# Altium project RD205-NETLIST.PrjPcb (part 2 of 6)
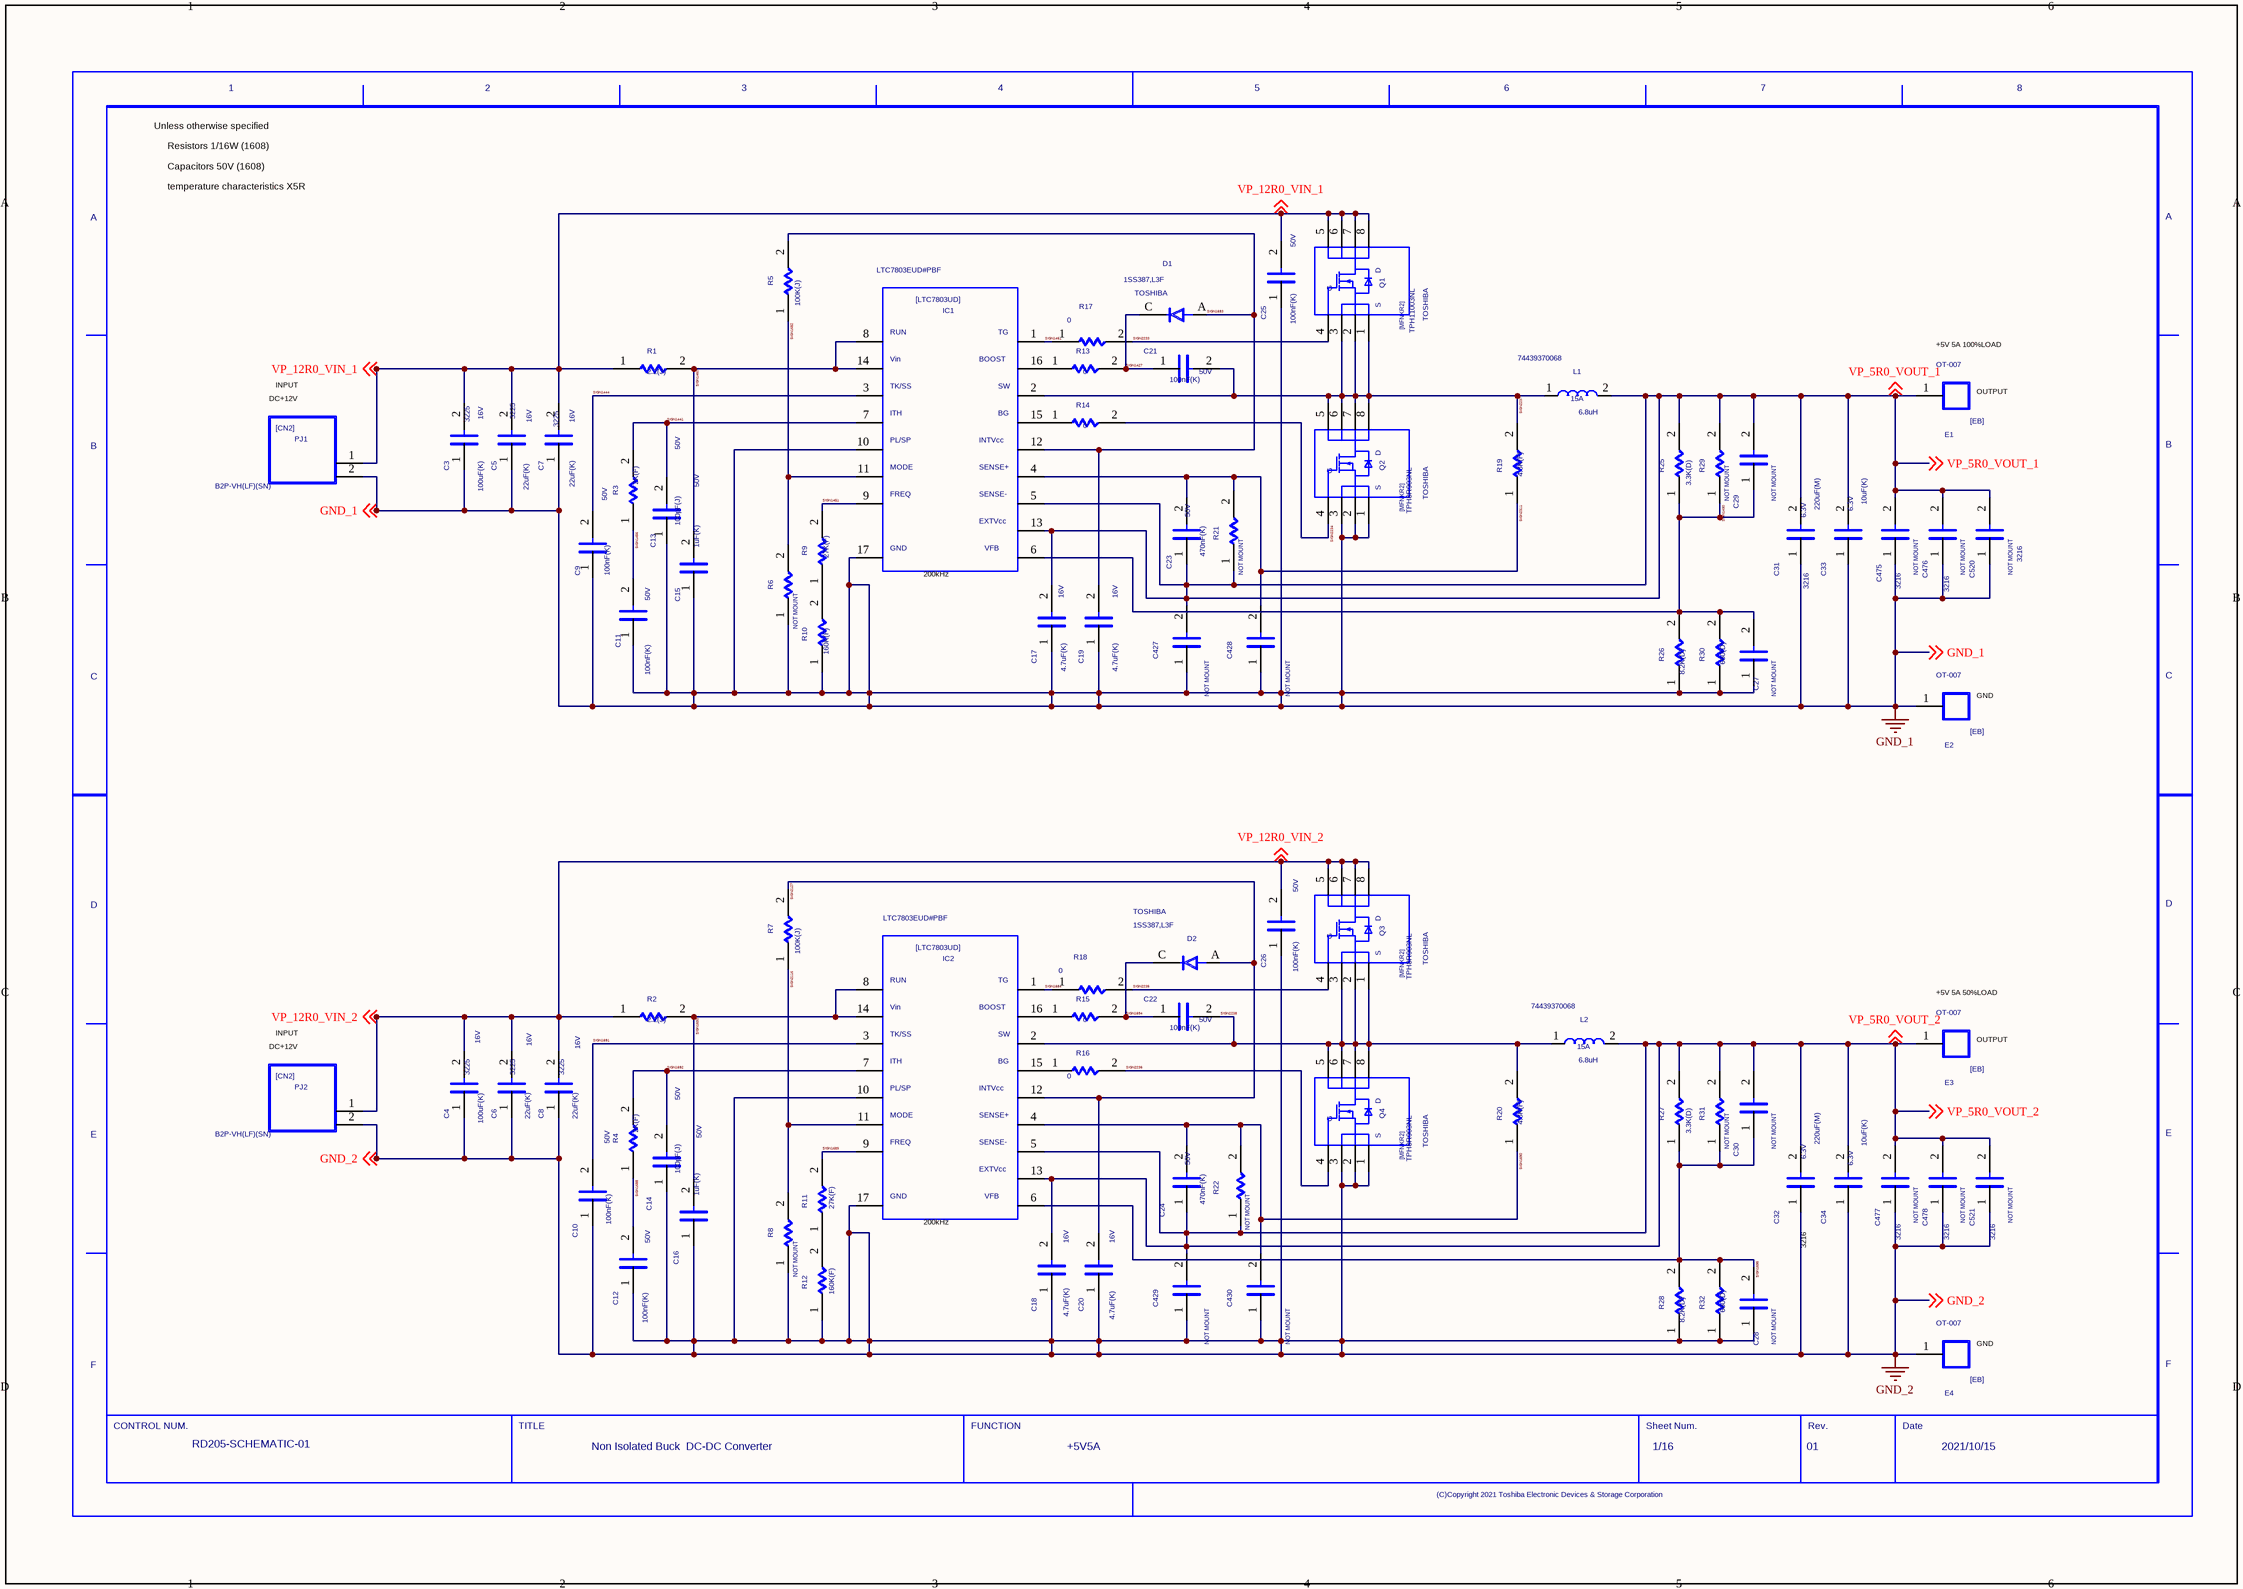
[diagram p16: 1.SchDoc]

## Sheet 1.SchDoc (continued)

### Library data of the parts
C3 = C_Dup1: SQ_PART_MODEL: CON_100n; FNPARTSNAMEG: CHIP CERAMIC CAPACITOR (3225); USEINPARTSLIST: YES; OriginalSymbolOrigin: (2540,7620); OLDCOMPONENTID: 209; MFSOLDERINGPROP: .; TEMPCHARACTERI2: B; MFFORMINGDIVP: KC; OUMECLASSIFICATION: セラミックコンデンサ; MFMOUNTSYMBOLP: 90; CDMASTERCADCELG: DC903A; PCODE: P03276001115; FNCLASSCODEG: P03-03; MAXGCOUNT: 1; RATEDVOLTAGE: 250; COMPONENTNAME: G36030160049; OUMEMAKER: KYC 京セラ; MFPACKAGEMETHOP: S; NOMINALCAPACITA: 100n; OUMEMAKERKATAMEI: CF32W5R104K250AT; CAPACITANCETOLE: K
C4 = C_Dup1: SQ_PART_MODEL: CON_100n; FNPARTSNAMEG: CHIP CERAMIC CAPACITOR (3225); USEINPARTSLIST: YES; OriginalSymbolOrigin: (2540,7620); OLDCOMPONENTID: 396; MFSOLDERINGPROP: .; TEMPCHARACTERI2: B; MFFORMINGDIVP: KC; OUMECLASSIFICATION: セラミックコンデンサ; MFMOUNTSYMBOLP: 90; CDMASTERCADCELG: DC903A; PCODE: P03276001115; FNCLASSCODEG: P03-03; MAXGCOUNT: 1; RATEDVOLTAGE: 250; COMPONENTNAME: G36030160049; OUMEMAKER: KYC 京セラ; MFPACKAGEMETHOP: S; NOMINALCAPACITA: 100n; OUMEMAKERKATAMEI: CF32W5R104K250AT; CAPACITANCETOLE: K
C5 = C_Dup1: SQ_PART_MODEL: CON_22u; FNPARTSNAMEG: CHIP CERAMIC CAPACITOR (3225); USEINPARTSLIST: YES; OriginalSymbolOrigin: (2540,7620); OLDCOMPONENTID: 195; MFSOLDERINGPROP: .; TEMPCHARACTERI2: B; MFFORMINGDIVP: KC; OUMECLASSIFICATION: セラミックコンデンサ; MFMOUNTSYMBOLP: 80; CDMASTERCADCELG: DC903A; PCODE: P03043035626; FNCLASSCODEG: P03-03; MAXGCOUNT: 1; RATEDVOLTAGE: 6.3; COMPONENTNAME: G36030119054; OUMEMAKER: TYD 太陽誘電; MFPACKAGEMETHOP: S; NOMINALCAPACITA: 22u; OUMEMAKERKATAMEI: JMK325BJ226KM-T; CAPACITANCETOLE: K
C6 = C_Dup1: SQ_PART_MODEL: CON_22u; FNPARTSNAMEG: CHIP CERAMIC CAPACITOR (3225); USEINPARTSLIST: YES; OriginalSymbolOrigin: (2540,7620); OLDCOMPONENTID: 358; MFSOLDERINGPROP: .; TEMPCHARACTERI2: B; MFFORMINGDIVP: KC; OUMECLASSIFICATION: セラミックコンデンサ; MFMOUNTSYMBOLP: 80; CDMASTERCADCELG: DC903A; PCODE: P03043035626; FNCLASSCODEG: P03-03; MAXGCOUNT: 1; RATEDVOLTAGE: 6.3; COMPONENTNAME: G36030119054; OUMEMAKER: TYD 太陽誘電; MFPACKAGEMETHOP: S; NOMINALCAPACITA: 22u; OUMEMAKERKATAMEI: JMK325BJ226KM-T; CAPACITANCETOLE: K
C7 = C_Dup1: SQ_PART_MODEL: CON_22u; FNPARTSNAMEG: CHIP CERAMIC CAPACITOR (3225); USEINPARTSLIST: YES; OriginalSymbolOrigin: (2540,7620); OLDCOMPONENTID: 230; MFSOLDERINGPROP: .; TEMPCHARACTERI2: B; MFFORMINGDIVP: KC; OUMECLASSIFICATION: セラミックコンデンサ; MFMOUNTSYMBOLP: 80; CDMASTERCADCELG: DC903A; PCODE: P03043035626; FNCLASSCODEG: P03-03; MAXGCOUNT: 1; RATEDVOLTAGE: 6.3; COMPONENTNAME: G36030119054; OUMEMAKER: TYD 太陽誘電; MFPACKAGEMETHOP: S; NOMINALCAPACITA: 22u; OUMEMAKERKATAMEI: JMK325BJ226KM-T; CAPACITANCETOLE: K
C8 = C_Dup1: SQ_PART_MODEL: CON_22u; FNPARTSNAMEG: CHIP CERAMIC CAPACITOR (3225); USEINPARTSLIST: YES; OriginalSymbolOrigin: (2540,7620); OLDCOMPONENTID: 386; MFSOLDERINGPROP: .; TEMPCHARACTERI2: B; MFFORMINGDIVP: KC; OUMECLASSIFICATION: セラミックコンデンサ; MFMOUNTSYMBOLP: 80; CDMASTERCADCELG: DC903A; PCODE: P03043035626; FNCLASSCODEG: P03-03; MAXGCOUNT: 1; RATEDVOLTAGE: 6.3; COMPONENTNAME: G36030119054; OUMEMAKER: TYD 太陽誘電; MFPACKAGEMETHOP: S; NOMINALCAPACITA: 22u; OUMEMAKERKATAMEI: JMK325BJ226KM-T; CAPACITANCETOLE: K
C9 = C_Dup1: SQ_PART_MODEL: CON_100n; FNPARTSNAMEG: CHIP CERAMIC CAPACITOR (1608); USEINPARTSLIST: YES; OriginalSymbolOrigin: (2540,7620); OLDCOMPONENTID: 199; MFSOLDERINGPROP: .; TEMPCHARACTERI2: B; MFFORMINGDIVP: KC; OUMECLASSIFICATION: セラミックコンデンサ; SIZECODESMD: 1608; MFMOUNTSYMBOLP: 80; CDMASTERCADCELG: C8100E; PCODE: P03B000000E4; FNCLASSCODEG: P03-03; MAXGCOUNT: 1; RATEDVOLTAGE: 16; COMPONENTNAME: GDM030000598; OUMEMAKER: MRT 村田製作所; MFPACKAGEMETHOP: S; NOMINALCAPACITA: 100n; OUMEMAKERKATAMEI: GRM188B11C104KA01C; CAPACITANCETOLE: K
C10 = C_Dup1: SQ_PART_MODEL: CON_100n; FNPARTSNAMEG: CHIP CERAMIC CAPACITOR (1608); USEINPARTSLIST: YES; OriginalSymbolOrigin: (2540,7620); OLDCOMPONENTID: 349; MFSOLDERINGPROP: .; TEMPCHARACTERI2: B; MFFORMINGDIVP: KC; OUMECLASSIFICATION: セラミックコンデンサ; SIZECODESMD: 1608; MFMOUNTSYMBOLP: 80; CDMASTERCADCELG: C8100E; PCODE: P03B000000E4; FNCLASSCODEG: P03-03; MAXGCOUNT: 1; RATEDVOLTAGE: 16; COMPONENTNAME: GDM030000598; OUMEMAKER: MRT 村田製作所; MFPACKAGEMETHOP: S; NOMINALCAPACITA: 100n; OUMEMAKERKATAMEI: GRM188B11C104KA01C; CAPACITANCETOLE: K
C11 = C_Dup1: SQ_PART_MODEL: CON_100n; FNPARTSNAMEG: CHIP CERAMIC CAPACITOR (1608); USEINPARTSLIST: YES; OriginalSymbolOrigin: (2540,7620); OLDCOMPONENTID: 173; MFSOLDERINGPROP: .; TEMPCHARACTERI2: B; MFFORMINGDIVP: KC; OUMECLASSIFICATION: セラミックコンデンサ; SIZECODESMD: 1608; MFMOUNTSYMBOLP: 80; CDMASTERCADCELG: C8100E; PCODE: P03B000000E4; FNCLASSCODEG: P03-03; MAXGCOUNT: 1; RATEDVOLTAGE: 16; COMPONENTNAME: GDM030000598; OUMEMAKER: MRT 村田製作所; MFPACKAGEMETHOP: S; NOMINALCAPACITA: 100n; OUMEMAKERKATAMEI: GRM188B11C104KA01C; CAPACITANCETOLE: K
C12 = C_Dup1: SQ_PART_MODEL: CON_100n; FNPARTSNAMEG: CHIP CERAMIC CAPACITOR (1608); USEINPARTSLIST: YES; OriginalSymbolOrigin: (2540,7620); OLDCOMPONENTID: 400; MFSOLDERINGPROP: .; TEMPCHARACTERI2: B; MFFORMINGDIVP: KC; OUMECLASSIFICATION: セラミックコンデンサ; SIZECODESMD: 1608; MFMOUNTSYMBOLP: 80; CDMASTERCADCELG: C8100E; PCODE: P03B000000E4; FNCLASSCODEG: P03-03; MAXGCOUNT: 1; RATEDVOLTAGE: 16; COMPONENTNAME: GDM030000598; OUMEMAKER: MRT 村田製作所; MFPACKAGEMETHOP: S; NOMINALCAPACITA: 100n; OUMEMAKERKATAMEI: GRM188B11C104KA01C; CAPACITANCETOLE: K
C13 = C_Dup1: SQ_PART_MODEL: CON_100p; FNPARTSNAMEG: CHIP CERAMIC CAPACITOR (1608); USEINPARTSLIST: YES; OriginalSymbolOrigin: (2540,7620); OLDCOMPONENTID: 206; TOLERANCE: J; ASIMVALUE: 100P; MFSOLDERINGPROP: .; TEMPCHARACTERI2: CH; MFFORMINGDIVP: KC; OUMECLASSIFICATION: セラミックコンデンサ; SIZECODESMD: 1608; MFMOUNTSYMBOLP: 80; CDMASTERCADCELG: C8100E; PCODE: P03039177125; FNCLASSCODEG: P03-03; MAXGCOUNT: 1; RATEDVOLTAGE: 50; COMPONENTNAME: G36030011365; OUMEMAKER: KYC 京セラ; MFPACKAGEMETHOP: S; OUMEMAKERKATAMEI: CM105CH101J50AT
C14 = C_Dup1: SQ_PART_MODEL: CON_100p; FNPARTSNAMEG: CHIP CERAMIC CAPACITOR (1608); USEINPARTSLIST: YES; OriginalSymbolOrigin: (2540,7620); OLDCOMPONENTID: 397; TOLERANCE: J; ASIMVALUE: 100P; MFSOLDERINGPROP: .; TEMPCHARACTERI2: CH; MFFORMINGDIVP: KC; OUMECLASSIFICATION: セラミックコンデンサ; SIZECODESMD: 1608; MFMOUNTSYMBOLP: 80; CDMASTERCADCELG: C8100E; PCODE: P03039177125; FNCLASSCODEG: P03-03; MAXGCOUNT: 1; RATEDVOLTAGE: 50; COMPONENTNAME: G36030011365; OUMEMAKER: KYC 京セラ; MFPACKAGEMETHOP: S; OUMEMAKERKATAMEI: CM105CH101J50AT
C15 = C_Dup1: SQ_PART_MODEL: CON_1u; FNPARTSNAMEG: CHIP CERAMIC CAPACITOR (1608); USEINPARTSLIST: YES; OriginalSymbolOrigin: (2540,7620); OLDCOMPONENTID: 176; MFSOLDERINGPROP: .; TEMPCHARACTERI2: B; MFFORMINGDIVP: KC; OUMECLASSIFICATION: セラミックコンデンサ; SIZECODESMD: 1608; MFMOUNTSYMBOLP: 80; CDMASTERCADCELG: C8100E; PCODE: P03039ACE122; FNCLASSCODEG: P03-03; MAXGCOUNT: 1; RATEDVOLTAGE: 6.3; COMPONENTNAME: G36030104159; OUMEMAKER: KYC 京セラ; MFPACKAGEMETHOP: S; NOMINALCAPACITA: 1u; OUMEMAKERKATAMEI: CM105B105K06ATN; CAPACITANCETOLE: K
C16 = C_Dup1: SQ_PART_MODEL: CON_1u; FNPARTSNAMEG: CHIP CERAMIC CAPACITOR (1608); USEINPARTSLIST: YES; OriginalSymbolOrigin: (2540,7620); OLDCOMPONENTID: 368; MFSOLDERINGPROP: .; TEMPCHARACTERI2: B; MFFORMINGDIVP: KC; OUMECLASSIFICATION: セラミックコンデンサ; SIZECODESMD: 1608; MFMOUNTSYMBOLP: 80; CDMASTERCADCELG: C8100E; PCODE: P03039ACE122; FNCLASSCODEG: P03-03; MAXGCOUNT: 1; RATEDVOLTAGE: 6.3; COMPONENTNAME: G36030104159; OUMEMAKER: KYC 京セラ; MFPACKAGEMETHOP: S; NOMINALCAPACITA: 1u; OUMEMAKERKATAMEI: CM105B105K06ATN; CAPACITANCETOLE: K
C17 = C_Dup1: SQ_PART_MODEL: CON_4.7u; FNPARTSNAMEG: CHIP CERAMIC CAPACITOR (1608); USEINPARTSLIST: YES; OriginalSymbolOrigin: (2540,7620); OLDCOMPONENTID: 178; PCODE: P03B000000MS; MFSOLDERINGPROP: .; TEMPCHARACTERI2: B; MFFORMINGDIVP: KC; OUMECLASSIFICATION: セラミックコンデンサ; SIZECODESMD: 1608; MFMOUNTSYMBOLP: 80; CDMASTERCADCELG: C8100E; FNCLASSCODEG: P03-03; MAXGCOUNT: 1; RATEDVOLTAGE: 4; COMPONENTNAME: GDM030000053; OUMEMAKER: KYC 京セラ; MFPACKAGEMETHOP: S; NOMINALCAPACITA: 4.7u; OUMEMAKERKATAMEI: CM105B475M04AT; CAPACITANCETOLE: M
C18 = C_Dup1: SQ_PART_MODEL: CON_4.7u; FNPARTSNAMEG: CHIP CERAMIC CAPACITOR (1608); USEINPARTSLIST: YES; OriginalSymbolOrigin: (2540,7620); OLDCOMPONENTID: 389; PCODE: P03B000000MS; MFSOLDERINGPROP: .; TEMPCHARACTERI2: B; MFFORMINGDIVP: KC; OUMECLASSIFICATION: セラミックコンデンサ; SIZECODESMD: 1608; MFMOUNTSYMBOLP: 80; CDMASTERCADCELG: C8100E; FNCLASSCODEG: P03-03; MAXGCOUNT: 1; RATEDVOLTAGE: 4; COMPONENTNAME: GDM030000053; OUMEMAKER: KYC 京セラ; MFPACKAGEMETHOP: S; NOMINALCAPACITA: 4.7u; OUMEMAKERKATAMEI: CM105B475M04AT; CAPACITANCETOLE: M
C19 = C_Dup1: SQ_PART_MODEL: CON_4.7u; FNPARTSNAMEG: CHIP CERAMIC CAPACITOR (1608); USEINPARTSLIST: YES; OriginalSymbolOrigin: (2540,7620); OLDCOMPONENTID: 153; MFSOLDERINGPROP: .; TEMPCHARACTERI2: B; MFFORMINGDIVP: KC; OUMECLASSIFICATION: セラミックコンデンサ; SIZECODESMD: 1608; MFMOUNTSYMBOLP: 80; CDMASTERCADCELG: C8100E; PCODE: P03B000000MS; FNCLASSCODEG: P03-03; MAXGCOUNT: 1; RATEDVOLTAGE: 4; COMPONENTNAME: GDM030000053; OUMEMAKER: KYC 京セラ; MFPACKAGEMETHOP: S; NOMINALCAPACITA: 4.7u; OUMEMAKERKATAMEI: CM105B475M04AT; CAPACITANCETOLE: M
C20 = C_Dup1: SQ_PART_MODEL: CON_4.7u; FNPARTSNAMEG: CHIP CERAMIC CAPACITOR (1608); USEINPARTSLIST: YES; OriginalSymbolOrigin: (2540,7620); OLDCOMPONENTID: 387; MFSOLDERINGPROP: .; TEMPCHARACTERI2: B; MFFORMINGDIVP: KC; OUMECLASSIFICATION: セラミックコンデンサ; SIZECODESMD: 1608; MFMOUNTSYMBOLP: 80; CDMASTERCADCELG: C8100E; PCODE: P03B000000MS; FNCLASSCODEG: P03-03; MAXGCOUNT: 1; RATEDVOLTAGE: 4; COMPONENTNAME: GDM030000053; OUMEMAKER: KYC 京セラ; MFPACKAGEMETHOP: S; NOMINALCAPACITA: 4.7u; OUMEMAKERKATAMEI: CM105B475M04AT; CAPACITANCETOLE: M
C21 = C_Dup1: SQ_PART_MODEL: CON_100n; FNPARTSNAMEG: CHIP CERAMIC CAPACITOR (1608); USEINPARTSLIST: YES; OriginalSymbolOrigin: (2540,7620); OLDCOMPONENTID: 163; MFSOLDERINGPROP: .; TEMPCHARACTERI2: B; MFFORMINGDIVP: KC; OUMECLASSIFICATION: セラミックコンデンサ; SIZECODESMD: 1608; MFMOUNTSYMBOLP: 80; CDMASTERCADCELG: C8100E; PCODE: P03B000000E4; FNCLASSCODEG: P03-03; MAXGCOUNT: 1; RATEDVOLTAGE: 16; COMPONENTNAME: GDM030000598; OUMEMAKER: MRT 村田製作所; MFPACKAGEMETHOP: S; NOMINALCAPACITA: 100n; OUMEMAKERKATAMEI: GRM188B11C104KA01C; CAPACITANCETOLE: K
C22 = C_Dup1: SQ_PART_MODEL: CON_100n; FNPARTSNAMEG: CHIP CERAMIC CAPACITOR (1608); USEINPARTSLIST: YES; OriginalSymbolOrigin: (2540,7620); OLDCOMPONENTID: 352; MFSOLDERINGPROP: .; TEMPCHARACTERI2: B; MFFORMINGDIVP: KC; OUMECLASSIFICATION: セラミックコンデンサ; SIZECODESMD: 1608; MFMOUNTSYMBOLP: 80; CDMASTERCADCELG: C8100E; PCODE: P03B000000E4; FNCLASSCODEG: P03-03; MAXGCOUNT: 1; RATEDVOLTAGE: 16; COMPONENTNAME: GDM030000598; OUMEMAKER: MRT 村田製作所; MFPACKAGEMETHOP: S; NOMINALCAPACITA: 100n; OUMEMAKERKATAMEI: GRM188B11C104KA01C; CAPACITANCETOLE: K
C23 = C_Dup1: SQ_PART_MODEL: CON_470n; FNPARTSNAMEG: CHIP CERAMIC CAPACITOR (1608); USEINPARTSLIST: YES; OriginalSymbolOrigin: (2540,7620); OLDCOMPONENTID: 208; MFSOLDERINGPROP: .; TEMPCHARACTERI2: B; MFFORMINGDIVP: KC; OUMECLASSIFICATION: セラミックコンデンサ; SIZECODESMD: 1608; MFMOUNTSYMBOLP: 80; CDMASTERCADCELG: C8100E; PCODE: P03039ABG127; FNCLASSCODEG: P03-03; MAXGCOUNT: 1; RATEDVOLTAGE: 10; COMPONENTNAME: GDM030001129; OUMEMAKER: KYC 京セラ; MFPACKAGEMETHOP: S; NOMINALCAPACITA: 470n; OUMEMAKERKATAMEI: CM105B474K10AT; CAPACITANCETOLE: K
C24 = C_Dup1: SQ_PART_MODEL: CON_470n; FNPARTSNAMEG: CHIP CERAMIC CAPACITOR (1608); USEINPARTSLIST: YES; OriginalSymbolOrigin: (2540,7620); OLDCOMPONENTID: 355; MFSOLDERINGPROP: .; TEMPCHARACTERI2: B; MFFORMINGDIVP: KC; OUMECLASSIFICATION: セラミックコンデンサ; SIZECODESMD: 1608; MFMOUNTSYMBOLP: 80; CDMASTERCADCELG: C8100E; PCODE: P03039ABG127; FNCLASSCODEG: P03-03; MAXGCOUNT: 1; RATEDVOLTAGE: 10; COMPONENTNAME: GDM030001129; OUMEMAKER: KYC 京セラ; MFPACKAGEMETHOP: S; NOMINALCAPACITA: 470n; OUMEMAKERKATAMEI: CM105B474K10AT; CAPACITANCETOLE: K
C25 = C_Dup1: SQ_PART_MODEL: CON_100n; FNPARTSNAMEG: CHIP CERAMIC CAPACITOR (1608); USEINPARTSLIST: YES; OriginalSymbolOrigin: (2540,7620); OLDCOMPONENTID: 336; MFSOLDERINGPROP: .; TEMPCHARACTERI2: B; MFFORMINGDIVP: KC; OUMECLASSIFICATION: セラミックコンデンサ; SIZECODESMD: 1608; MFMOUNTSYMBOLP: 80; CDMASTERCADCELG: C8100E; PCODE: P03B000000E4; FNCLASSCODEG: P03-03; MAXGCOUNT: 1; RATEDVOLTAGE: 16; COMPONENTNAME: GDM030000598; OUMEMAKER: MRT 村田製作所; MFPACKAGEMETHOP: S; NOMINALCAPACITA: 100n; OUMEMAKERKATAMEI: GRM188B11C104KA01C; CAPACITANCETOLE: K
C26 = C_Dup1: SQ_PART_MODEL: CON_100n; FNPARTSNAMEG: CHIP CERAMIC CAPACITOR (1608); USEINPARTSLIST: YES; OriginalSymbolOrigin: (2540,7620); OLDCOMPONENTID: 359; MFSOLDERINGPROP: .; TEMPCHARACTERI2: B; MFFORMINGDIVP: KC; OUMECLASSIFICATION: セラミックコンデンサ; SIZECODESMD: 1608; MFMOUNTSYMBOLP: 80; CDMASTERCADCELG: C8100E; PCODE: P03B000000E4; FNCLASSCODEG: P03-03; MAXGCOUNT: 1; RATEDVOLTAGE: 16; COMPONENTNAME: GDM030000598; OUMEMAKER: MRT 村田製作所; MFPACKAGEMETHOP: S; NOMINALCAPACITA: 100n; OUMEMAKERKATAMEI: GRM188B11C104KA01C; CAPACITANCETOLE: K
C27 = C_Dup1: SQ_PART_MODEL: CON_100p; FNPARTSNAMEG: CHIP CERAMIC CAPACITOR (1608); USEINPARTSLIST: YES; OriginalSymbolOrigin: (2540,7620); OLDCOMPONENTID: 425; TOLERANCE: J; ASIMVALUE: 100P; MFSOLDERINGPROP: .; TEMPCHARACTERI2: CH; MFFORMINGDIVP: KC; OUMECLASSIFICATION: セラミックコンデンサ; SIZECODESMD: 1608; MFMOUNTSYMBOLP: 80; CDMASTERCADCELG: C8100E; PCODE: P03039177125; FNCLASSCODEG: P03-03; MAXGCOUNT: 1; RATEDVOLTAGE: 50; COMPONENTNAME: G36030011365; OUMEMAKER: KYC 京セラ; MFPACKAGEMETHOP: S; OUMEMAKERKATAMEI: CM105CH101J50AT; VAL2: 50V; VAL1: 100pF(J)
C28 = C_Dup1: SQ_PART_MODEL: CON_100p; FNPARTSNAMEG: CHIP CERAMIC CAPACITOR (1608); USEINPARTSLIST: YES; OriginalSymbolOrigin: (2540,7620); OLDCOMPONENTID: 427; TOLERANCE: J; ASIMVALUE: 100P; MFSOLDERINGPROP: .; TEMPCHARACTERI2: CH; MFFORMINGDIVP: KC; OUMECLASSIFICATION: セラミックコンデンサ; SIZECODESMD: 1608; MFMOUNTSYMBOLP: 80; CDMASTERCADCELG: C8100E; PCODE: P03039177125; FNCLASSCODEG: P03-03; MAXGCOUNT: 1; RATEDVOLTAGE: 50; COMPONENTNAME: G36030011365; OUMEMAKER: KYC 京セラ; MFPACKAGEMETHOP: S; OUMEMAKERKATAMEI: CM105CH101J50AT; VAL2: 50V; VAL1: 100pF(J)
C29 = C_Dup1: SQ_PART_MODEL: CON_100p; FNPARTSNAMEG: CHIP CERAMIC CAPACITOR (1608); USEINPARTSLIST: YES; OriginalSymbolOrigin: (2540,7620); OLDCOMPONENTID: 424; TOLERANCE: J; ASIMVALUE: 100P; MFSOLDERINGPROP: .; TEMPCHARACTERI2: CH; MFFORMINGDIVP: KC; OUMECLASSIFICATION: セラミックコンデンサ; SIZECODESMD: 1608; MFMOUNTSYMBOLP: 80; CDMASTERCADCELG: C8100E; PCODE: P03039177125; FNCLASSCODEG: P03-03; MAXGCOUNT: 1; RATEDVOLTAGE: 50; COMPONENTNAME: G36030011365; OUMEMAKER: KYC 京セラ; MFPACKAGEMETHOP: S; OUMEMAKERKATAMEI: CM105CH101J50AT; VAL2: 50V; VAL1: 100pF(J)
C30 = C_Dup1: SQ_PART_MODEL: CON_100p; FNPARTSNAMEG: CHIP CERAMIC CAPACITOR (1608); USEINPARTSLIST: YES; OriginalSymbolOrigin: (2540,7620); OLDCOMPONENTID: 426; TOLERANCE: J; ASIMVALUE: 100P; MFSOLDERINGPROP: .; TEMPCHARACTERI2: CH; MFFORMINGDIVP: KC; OUMECLASSIFICATION: セラミックコンデンサ; SIZECODESMD: 1608; MFMOUNTSYMBOLP: 80; CDMASTERCADCELG: C8100E; PCODE: P03039177125; FNCLASSCODEG: P03-03; MAXGCOUNT: 1; RATEDVOLTAGE: 50; COMPONENTNAME: G36030011365; OUMEMAKER: KYC 京セラ; MFPACKAGEMETHOP: S; OUMEMAKERKATAMEI: CM105CH101J50AT; VAL2: 50V; VAL1: 100pF(J)
C31 = C_Dup1: SQ_PART_MODEL: CON_22u; FNPARTSNAMEG: CHIP CERAMIC CAPACITOR (3216); USEINPARTSLIST: YES; OriginalSymbolOrigin: (2540,7620); OLDCOMPONENTID: 182; MFSOLDERINGPROP: .; TEMPCHARACTERI2: B; MFFORMINGDIVP: KC; OUMECLASSIFICATION: セラミックコンデンサ; MFMOUNTSYMBOLP: 80; CDMASTERCADCELG: DC901A; PCODE: P03B0000004V; FNCLASSCODEG: P03-03; MAXGCOUNT: 1; RATEDVOLTAGE: 6.3; COMPONENTNAME: GDM030000020; OUMEMAKER: KYC 京セラ; MFPACKAGEMETHOP: S; NOMINALCAPACITA: 22u; OUMEMAKERKATAMEI: CM316B226M06AT; CAPACITANCETOLE: M
C32 = C_Dup1: SQ_PART_MODEL: CON_22u; FNPARTSNAMEG: CHIP CERAMIC CAPACITOR (3216); USEINPARTSLIST: YES; OriginalSymbolOrigin: (2540,7620); OLDCOMPONENTID: 372; MFSOLDERINGPROP: .; TEMPCHARACTERI2: B; MFFORMINGDIVP: KC; OUMECLASSIFICATION: セラミックコンデンサ; SIZECODESMD: 3216; MFMOUNTSYMBOLP: 80; CDMASTERCADCELG: DC901A; PCODE: P03B0000004V; FNCLASSCODEG: P03-03; MAXGCOUNT: 1; RATEDVOLTAGE: 6.3; COMPONENTNAME: GDM030000020; OUMEMAKER: KYC 京セラ; MFPACKAGEMETHOP: S; NOMINALCAPACITA: 22u; OUMEMAKERKATAMEI: CM316B226M06AT; CAPACITANCETOLE: M
C33 = C_Dup1: SQ_PART_MODEL: CON_1u; FNPARTSNAMEG: CHIP CERAMIC CAPACITOR (1608); PARTCOMMENT: 代表セル<KC0008> がフットプリントに登録されていません。; USEINPARTSLIST: YES; OriginalSymbolOrigin: (2540,7620); OLDCOMPONENTID: 165; MFSOLDERINGPROP: .; TEMPCHARACTERI2: B; MFFORMINGDIVP: KC; OUMECLASSIFICATION: セラミックコンデンサ; SIZECODESMD: 1608; MFMOUNTSYMBOLP: 80; CDMASTERCADCELG: KC0008; PCODE: P03B000000ZQ; FNCLASSCODEG: P03-03; MAXGCOUNT: 1; RATEDVOLTAGE: 6.3; COMPONENTNAME: GDM030000202; OUMEMAKER: MRT 村田製作所; MFPACKAGEMETHOP: S; NOMINALCAPACITA: 1u; OUMEMAKERKATAMEI: GRM185B10J105KE21D; CAPACITANCETOLE: K
C34 = C_Dup1: SQ_PART_MODEL: CON_1u; FNPARTSNAMEG: CHIP CERAMIC CAPACITOR (1608); PARTCOMMENT: 代表セル<KC0008> がフットプリントに登録されていません。; USEINPARTSLIST: YES; OriginalSymbolOrigin: (2540,7620); OLDCOMPONENTID: 385; MFSOLDERINGPROP: .; TEMPCHARACTERI2: B; MFFORMINGDIVP: KC; OUMECLASSIFICATION: セラミックコンデンサ; SIZECODESMD: 1608; MFMOUNTSYMBOLP: 80; CDMASTERCADCELG: KC0008; PCODE: P03B000000ZQ; FNCLASSCODEG: P03-03; MAXGCOUNT: 1; RATEDVOLTAGE: 6.3; COMPONENTNAME: GDM030000202; OUMEMAKER: MRT 村田製作所; MFPACKAGEMETHOP: S; NOMINALCAPACITA: 1u; OUMEMAKERKATAMEI: GRM185B10J105KE21D; CAPACITANCETOLE: K
C427 = C_Dup1: SQ_PART_MODEL: CON_220n; FNPARTSNAMEG: CHIP CERAMIC CAPACITOR (1608); PARTCOMMENT: 代表セル<KC0008> がフットプリントに登録されていません。; USEINPARTSLIST: YES; OriginalSymbolOrigin: (2540,7620); OLDCOMPONENTID: 428; MFSOLDERINGPROP: .; TEMPCHARACTERI2: B; MFFORMINGDIVP: KC; OUMECLASSIFICATION: セラミックコンデンサ; SIZECODESMD: 1608; MFMOUNTSYMBOLP: 80; CDMASTERCADCELG: KC0008; PCODE: P03B000001L3; FNCLASSCODEG: P03-03; MAXGCOUNT: 1; RATEDVOLTAGE: 16; COMPONENTNAME: GDM030001129; OUMEMAKER: MRT 村田製作所; MFPACKAGEMETHOP: S; NOMINALCAPACITA: 220n; OUMEMAKERKATAMEI: GRM188B11C224KA01D; VAL2: 16V; VAL1: 220nF(K); CAPACITANCETOLE: K
C428 = C_Dup1: SQ_PART_MODEL: CON_220n; FNPARTSNAMEG: CHIP CERAMIC CAPACITOR (1608); PARTCOMMENT: 代表セル<KC0008> がフットプリントに登録されていません。; USEINPARTSLIST: YES; OriginalSymbolOrigin: (2540,7620); OLDCOMPONENTID: 429; MFSOLDERINGPROP: .; TEMPCHARACTERI2: B; MFFORMINGDIVP: KC; OUMECLASSIFICATION: セラミックコンデンサ; SIZECODESMD: 1608; MFMOUNTSYMBOLP: 80; CDMASTERCADCELG: KC0008; PCODE: P03B000001L3; FNCLASSCODEG: P03-03; MAXGCOUNT: 1; RATEDVOLTAGE: 16; COMPONENTNAME: GDM030001129; OUMEMAKER: MRT 村田製作所; MFPACKAGEMETHOP: S; NOMINALCAPACITA: 220n; OUMEMAKERKATAMEI: GRM188B11C224KA01D; VAL2: 16V; VAL1: 220nF(K); CAPACITANCETOLE: K
C429 = C_Dup1: SQ_PART_MODEL: CON_220n; FNPARTSNAMEG: CHIP CERAMIC CAPACITOR (1608); PARTCOMMENT: 代表セル<KC0008> がフットプリントに登録されていません。; USEINPARTSLIST: YES; OriginalSymbolOrigin: (2540,7620); OLDCOMPONENTID: 431; MFSOLDERINGPROP: .; TEMPCHARACTERI2: B; MFFORMINGDIVP: KC; OUMECLASSIFICATION: セラミックコンデンサ; SIZECODESMD: 1608; MFMOUNTSYMBOLP: 80; CDMASTERCADCELG: KC0008; PCODE: P03B000001L3; FNCLASSCODEG: P03-03; MAXGCOUNT: 1; RATEDVOLTAGE: 16; COMPONENTNAME: GDM030001129; OUMEMAKER: MRT 村田製作所; MFPACKAGEMETHOP: S; NOMINALCAPACITA: 220n; OUMEMAKERKATAMEI: GRM188B11C224KA01D; VAL2: 16V; VAL1: 220nF(K); CAPACITANCETOLE: K
C430 = C_Dup1: SQ_PART_MODEL: CON_220n; FNPARTSNAMEG: CHIP CERAMIC CAPACITOR (1608); PARTCOMMENT: 代表セル<KC0008> がフットプリントに登録されていません。; USEINPARTSLIST: YES; OriginalSymbolOrigin: (2540,7620); OLDCOMPONENTID: 430; MFSOLDERINGPROP: .; TEMPCHARACTERI2: B; MFFORMINGDIVP: KC; OUMECLASSIFICATION: セラミックコンデンサ; SIZECODESMD: 1608; MFMOUNTSYMBOLP: 80; CDMASTERCADCELG: KC0008; PCODE: P03B000001L3; FNCLASSCODEG: P03-03; MAXGCOUNT: 1; RATEDVOLTAGE: 16; COMPONENTNAME: GDM030001129; OUMEMAKER: MRT 村田製作所; MFPACKAGEMETHOP: S; NOMINALCAPACITA: 220n; OUMEMAKERKATAMEI: GRM188B11C224KA01D; VAL2: 16V; VAL1: 220nF(K); CAPACITANCETOLE: K
C475 = C_Dup1: SQ_PART_MODEL: CON_22u; FNPARTSNAMEG: CHIP CERAMIC CAPACITOR (3216); USEINPARTSLIST: YES; OriginalSymbolOrigin: (2540,7620); OLDCOMPONENTID: 432; MFSOLDERINGPROP: .; TEMPCHARACTERI2: B; MFFORMINGDIVP: KC; OUMECLASSIFICATION: セラミックコンデンサ; MFMOUNTSYMBOLP: 80; CDMASTERCADCELG: DC901A; PCODE: P03B0000004V; FNCLASSCODEG: P03-03; MAXGCOUNT: 1; RATEDVOLTAGE: 6.3; COMPONENTNAME: GDM030000020; OUMEMAKER: KYC 京セラ; MFPACKAGEMETHOP: S; NOMINALCAPACITA: 22u; OUMEMAKERKATAMEI: CM316B226M06AT; VAL2: 6.3V; VAL1: 22uF(M); CAPACITANCETOLE: M
C476 = C_Dup1: SQ_PART_MODEL: CON_22u; FNPARTSNAMEG: CHIP CERAMIC CAPACITOR (3216); USEINPARTSLIST: YES; OriginalSymbolOrigin: (2540,7620); OLDCOMPONENTID: 434; MFSOLDERINGPROP: .; TEMPCHARACTERI2: B; MFFORMINGDIVP: KC; OUMECLASSIFICATION: セラミックコンデンサ; MFMOUNTSYMBOLP: 80; CDMASTERCADCELG: DC901A; PCODE: P03B0000004V; FNCLASSCODEG: P03-03; MAXGCOUNT: 1; RATEDVOLTAGE: 6.3; COMPONENTNAME: GDM030000020; OUMEMAKER: KYC 京セラ; MFPACKAGEMETHOP: S; NOMINALCAPACITA: 22u; OUMEMAKERKATAMEI: CM316B226M06AT; VAL2: 6.3V; VAL1: 22uF(M); CAPACITANCETOLE: M
C477 = C_Dup1: SQ_PART_MODEL: CON_22u; FNPARTSNAMEG: CHIP CERAMIC CAPACITOR (3216); USEINPARTSLIST: YES; OriginalSymbolOrigin: (2540,7620); OLDCOMPONENTID: 436; MFSOLDERINGPROP: .; TEMPCHARACTERI2: B; MFFORMINGDIVP: KC; OUMECLASSIFICATION: セラミックコンデンサ; MFMOUNTSYMBOLP: 80; CDMASTERCADCELG: DC901A; PCODE: P03B0000004V; FNCLASSCODEG: P03-03; MAXGCOUNT: 1; RATEDVOLTAGE: 6.3; COMPONENTNAME: GDM030000020; OUMEMAKER: KYC 京セラ; MFPACKAGEMETHOP: S; NOMINALCAPACITA: 22u; OUMEMAKERKATAMEI: CM316B226M06AT; VAL2: 6.3V; VAL1: 22uF(M); CAPACITANCETOLE: M
C478 = C_Dup1: SQ_PART_MODEL: CON_22u; FNPARTSNAMEG: CHIP CERAMIC CAPACITOR (3216); USEINPARTSLIST: YES; OriginalSymbolOrigin: (2540,7620); OLDCOMPONENTID: 435; MFSOLDERINGPROP: .; TEMPCHARACTERI2: B; MFFORMINGDIVP: KC; OUMECLASSIFICATION: セラミックコンデンサ; MFMOUNTSYMBOLP: 80; CDMASTERCADCELG: DC901A; PCODE: P03B0000004V; FNCLASSCODEG: P03-03; MAXGCOUNT: 1; RATEDVOLTAGE: 6.3; COMPONENTNAME: GDM030000020; OUMEMAKER: KYC 京セラ; MFPACKAGEMETHOP: S; NOMINALCAPACITA: 22u; OUMEMAKERKATAMEI: CM316B226M06AT; VAL2: 6.3V; VAL1: 22uF(M); CAPACITANCETOLE: M
C520 = C_Dup1: SQ_PART_MODEL: CON_22u; FNPARTSNAMEG: CHIP CERAMIC CAPACITOR (3216); USEINPARTSLIST: YES; OriginalSymbolOrigin: (2540,7620); OLDCOMPONENTID: 437; MFSOLDERINGPROP: .; TEMPCHARACTERI2: B; MFFORMINGDIVP: KC; OUMECLASSIFICATION: セラミックコンデンサ; MFMOUNTSYMBOLP: 80; CDMASTERCADCELG: DC901A; PCODE: P03B0000004V; FNCLASSCODEG: P03-03; MAXGCOUNT: 1; RATEDVOLTAGE: 6.3; COMPONENTNAME: GDM030000020; OUMEMAKER: KYC 京セラ; MFPACKAGEMETHOP: S; NOMINALCAPACITA: 22u; OUMEMAKERKATAMEI: CM316B226M06AT; VAL2: 6.3V; VAL1: 22uF(M); CAPACITANCETOLE: M
C521 = C_Dup1: SQ_PART_MODEL: CON_22u; FNPARTSNAMEG: CHIP CERAMIC CAPACITOR (3216); USEINPARTSLIST: YES; OriginalSymbolOrigin: (2540,7620); OLDCOMPONENTID: 438; MFSOLDERINGPROP: .; TEMPCHARACTERI2: B; MFFORMINGDIVP: KC; OUMECLASSIFICATION: セラミックコンデンサ; MFMOUNTSYMBOLP: 80; CDMASTERCADCELG: DC901A; PCODE: P03B0000004V; FNCLASSCODEG: P03-03; MAXGCOUNT: 1; RATEDVOLTAGE: 6.3; COMPONENTNAME: GDM030000020; OUMEMAKER: KYC 京セラ; MFPACKAGEMETHOP: S; NOMINALCAPACITA: 22u; OUMEMAKERKATAMEI: CM316B226M06AT; VAL2: 6.3V; VAL1: 22uF(M); CAPACITANCETOLE: M
D1 = D_Dup1: FNPARTSNAMEG: DIODE; USEINPARTSLIST: YES; PARTNAME: GDM420000143; SAVEAREA0: -565,-171,12979,8058; SAVECOUNT: 1; OriginalSymbolOrigin: (2540,5080); OLDCOMPONENTID: 415; FORWARDVOLTAGEM: 0; MAXREVERSEVOLTA: 80; COMPONENTNAME: GDM420000143_package; MFSOLDERINGPROP: .; OUMEMAKER: TSB 東芝（ＹＰＳＳ）; QUADMODEL: dummymodel; MFPACKAGEMETHOP: S; MFFORMINGDIVP: MM; MOUNTINGFORMSMD: SMD; OUMECLASSIFICATION: 小信号ダイオード; OUMEMAKERKATAMEI: 1SS387(TPH3,F); CDMASTERCADCELG: D8101D; PCODE: P42B0000008E; FNCLASSCODEG: P42-01
D2 = D_Dup1: FNPARTSNAMEG: DIODE; USEINPARTSLIST: YES; PARTNAME: GDM420000143; SAVEAREA0: -565,-171,12979,8058; SAVECOUNT: 1; OriginalSymbolOrigin: (2540,5080); OLDCOMPONENTID: 416; FORWARDVOLTAGEM: 0; MAXREVERSEVOLTA: 80; COMPONENTNAME: GDM420000143_package; MFSOLDERINGPROP: .; OUMEMAKER: TSB 東芝（ＹＰＳＳ）; QUADMODEL: dummymodel; MFPACKAGEMETHOP: S; MFFORMINGDIVP: MM; MOUNTINGFORMSMD: SMD; OUMECLASSIFICATION: 小信号ダイオード; OUMEMAKERKATAMEI: 1SS387(TPH3,F); CDMASTERCADCELG: D8101D; PCODE: P42B0000008E; FNCLASSCODEG: P42-01
E1 = EB_Dup1: FNPARTSNAMEG: TERMINAL; USEINPARTSLIST: YES; PARTNAME: 5P9L1232P001; OUMEPARTTYPE: TB; OriginalSymbolOrigin: (2540,12700); OLDCOMPONENTID: 155; COMPONENTNAME: 5P9L1232P001_package; MAXGCOUNT: 1; MFSOLDERINGPROP: .; OUMEMAKER: オサダ; QUADMODEL: dummymodel; MFPACKAGEMETHOP: I; MFFORMINGDIVP: OD; OUMECLASSIFICATION: 端子台、端子板; CDMASTERCADCELG: DE0009; KIND: PBS; PCODE: P29045001117; TERMINALSTYLE: SC; FNCLASSCODEG: P29-01
E2 = EB_Dup1: FNPARTSNAMEG: TERMINAL; USEINPARTSLIST: YES; PARTNAME: 5P9L1232P001; OUMEPARTTYPE: TB; OriginalSymbolOrigin: (2540,12700); OLDCOMPONENTID: 170; COMPONENTNAME: 5P9L1232P001_package; MAXGCOUNT: 1; MFSOLDERINGPROP: .; OUMEMAKER: オサダ; QUADMODEL: dummymodel; MFPACKAGEMETHOP: I; MFFORMINGDIVP: OD; OUMECLASSIFICATION: 端子台、端子板; CDMASTERCADCELG: DE0009; KIND: PBS; PCODE: P29045001117; TERMINALSTYLE: SC; FNCLASSCODEG: P29-01
E3 = EB_Dup1: FNPARTSNAMEG: TERMINAL; USEINPARTSLIST: YES; PARTNAME: 5P9L1232P001; OUMEPARTTYPE: TB; OriginalSymbolOrigin: (2540,12700); OLDCOMPONENTID: 356; COMPONENTNAME: 5P9L1232P001_package; MAXGCOUNT: 1; MFSOLDERINGPROP: .; OUMEMAKER: オサダ; QUADMODEL: dummymodel; MFPACKAGEMETHOP: I; MFFORMINGDIVP: OD; OUMECLASSIFICATION: 端子台、端子板; CDMASTERCADCELG: DE0009; KIND: PBS; PCODE: P29045001117; TERMINALSTYLE: SC; FNCLASSCODEG: P29-01
E4 = EB_Dup1: FNPARTSNAMEG: TERMINAL; USEINPARTSLIST: YES; PARTNAME: 5P9L1232P001; OUMEPARTTYPE: TB; OriginalSymbolOrigin: (2540,12700); OLDCOMPONENTID: 357; COMPONENTNAME: 5P9L1232P001_package; MAXGCOUNT: 1; MFSOLDERINGPROP: .; OUMEMAKER: オサダ; QUADMODEL: dummymodel; MFPACKAGEMETHOP: I; MFFORMINGDIVP: OD; OUMECLASSIFICATION: 端子台、端子板; CDMASTERCADCELG: DE0009; KIND: PBS; PCODE: P29045001117; TERMINALSTYLE: SC; FNCLASSCODEG: P29-01
IC1 = LTC7803UD: USEINPARTSLIST: YES; SAVECOUNT: 29; SAVEAREA0: -53177,0,89020,58420; TIME: 16:14:14; UPDATEUSER: q91866sr; UPDATETIME: 13:15:36; OriginalSymbolOrigin: (5080,55880); OLDCOMPONENTID: 421; MAXGCOUNT: 1; COMPONENTNAME: LTC7803UD_LTC7803UD; OUMEMAKER: ANALOG DEVICES
IC2 = LTC7803UD: USEINPARTSLIST: YES; SAVECOUNT: 29; SAVEAREA0: -53177,0,89020,58420; TIME: 16:14:14; UPDATEUSER: q91866sr; UPDATETIME: 13:15:36; OriginalSymbolOrigin: (5080,55880); OLDCOMPONENTID: 423; MAXGCOUNT: 1; COMPONENTNAME: LTC7803UD_LTC7803UD; OUMEMAKER: ANALOG DEVICES
L1 = L_Dup1: USEINPARTSLIST: YES; OriginalSymbolOrigin: (2540,5080); OLDCOMPONENTID: 193; MAXGCOUNT: 1; COMPONENTNAME: L_L; OUMEMAKER: WURTH
L2 = L_Dup1: USEINPARTSLIST: YES; OriginalSymbolOrigin: (2540,5080); OLDCOMPONENTID: 375; MAXGCOUNT: 1; COMPONENTNAME: L_L; OUMEMAKER: WURTH
PJ1 = CN2_Dup1: FNPARTSNAMEG: 3.96PITCH NYLON CONNECTOR; USEINPARTSLIST: YES; PARTNAME: G36220114012; OUMEPARTTYPE: CN; OriginalSymbolOrigin: (2540,15240); OLDCOMPONENTID: 161; MAXGCOUNT: 1; RATEDCURRENT: 7; COMPONENTNAME: G36220114012_package; MFSOLDERINGPROP: .; OUMEMAKER: JST 日本圧着端子製造; NUMBEROFCONTACT: 2; QUADMODEL: dummymodel; MFPACKAGEMETHOP: I; MFFORMINGDIVP: CU; CONTACTPITCH: 3.96m; OUMEMAKERKATAMEI: B2P-VH; CDMASTERCADCELG: DPJ514; PCODE: P22346001114; TERMINALSTYLE: PW; FNCLASSCODEG: P22-10
PJ2 = CN2_Dup1: FNPARTSNAMEG: 3.96PITCH NYLON CONNECTOR; USEINPARTSLIST: YES; PARTNAME: G36220114012; OUMEPARTTYPE: CN; OriginalSymbolOrigin: (2540,15240); OLDCOMPONENTID: 392; MAXGCOUNT: 1; RATEDCURRENT: 7; COMPONENTNAME: G36220114012_package; MFSOLDERINGPROP: .; OUMEMAKER: JST 日本圧着端子製造; NUMBEROFCONTACT: 2; QUADMODEL: dummymodel; MFPACKAGEMETHOP: I; MFFORMINGDIVP: CU; CONTACTPITCH: 3.96m; OUMEMAKERKATAMEI: B2P-VH; CDMASTERCADCELG: DPJ514; PCODE: P22346001114; TERMINALSTYLE: PW; FNCLASSCODEG: P22-10
Q1 = MFNKR2: USEINPARTSLIST: YES; PARTNAME: TPH6R003NL; SAVEAREA0: -9199,-39,32138,22820; TIME: 18:57:44; UPDATEUSER: q91866sr; UPDATETIME: 12:36:02; SAVECOUNT: 10; OriginalSymbolOrigin: (5080,20320); OLDCOMPONENTID: 325; MAXGCOUNT: 1; COMPONENTNAME: MFNKR2_MFNKR2
Q2 = MFNKR2: USEINPARTSLIST: YES; PARTNAME: TPH6R003NL; SAVEAREA0: -9199,-39,32138,22820; TIME: 18:57:44; UPDATEUSER: q91866sr; UPDATETIME: 12:36:02; SAVECOUNT: 10; OriginalSymbolOrigin: (5080,20320); OLDCOMPONENTID: 326; MAXGCOUNT: 1; COMPONENTNAME: MFNKR2_MFNKR2
Q3 = MFNKR2: USEINPARTSLIST: YES; PARTNAME: TPH6R003NL; SAVEAREA0: -9199,-39,32138,22820; TIME: 18:57:44; UPDATEUSER: q91866sr; UPDATETIME: 12:36:02; SAVECOUNT: 10; OriginalSymbolOrigin: (5080,20320); OLDCOMPONENTID: 440; MAXGCOUNT: 1; COMPONENTNAME: MFNKR2_MFNKR2
Q4 = MFNKR2: USEINPARTSLIST: YES; PARTNAME: TPH6R003NL; SAVEAREA0: -9199,-39,32138,22820; TIME: 18:57:44; UPDATEUSER: q91866sr; UPDATETIME: 12:36:02; SAVECOUNT: 10; OriginalSymbolOrigin: (5080,20320); OLDCOMPONENTID: 439; MAXGCOUNT: 1; COMPONENTNAME: MFNKR2_MFNKR2
R1 = R_Dup1: SQ_PART_MODEL: RES_2.2; FNPARTSNAMEG: CHIP RESISTOR (1608); USEINPARTSLIST: YES; OriginalSymbolOrigin: (5080,5080); OLDCOMPONENTID: 210; TOLERANCE: J; ASIMVALUE: 2.2; MAXGCOUNT: 1; COMPONENTNAME: G36010011507; MFSOLDERINGPROP: .; OUMEMAKER: NAE 松下電子部品; MFPACKAGEMETHOP: S; MFFORMINGDIVP: KC; MOUNTINGFORMSMD: SMD; OUMECLASSIFICATION: 表面実装用固定抵抗器; MFMOUNTSYMBOLP: 80; POWERRATING: 63m; OUMEMAKERKATAMEI: ERJ3GEYJ2R2V; NUMBEROFELEMENT: 0; VAL2: 62.5mW; CDMASTERCADCELG: DR802R; PCODE: P01042157622; FNCLASSCODEG: P01-08
R2 = R_Dup1: SQ_PART_MODEL: RES_2.2; FNPARTSNAMEG: CHIP RESISTOR (1608); USEINPARTSLIST: YES; OriginalSymbolOrigin: (5080,5080); OLDCOMPONENTID: 346; TOLERANCE: J; ASIMVALUE: 2.2; MAXGCOUNT: 1; COMPONENTNAME: G36010011507; MFSOLDERINGPROP: .; OUMEMAKER: NAE 松下電子部品; MFPACKAGEMETHOP: S; MFFORMINGDIVP: KC; MOUNTINGFORMSMD: SMD; OUMECLASSIFICATION: 表面実装用固定抵抗器; MFMOUNTSYMBOLP: 80; POWERRATING: 63m; OUMEMAKERKATAMEI: ERJ3GEYJ2R2V; NUMBEROFELEMENT: 0; VAL2: 62.5mW; CDMASTERCADCELG: DR802R; PCODE: P01042157622; FNCLASSCODEG: P01-08
R3 = R_Dup1: SQ_PART_MODEL: RES_2K; FNPARTSNAMEG: CHIP RESISTOR (1608); USEINPARTSLIST: YES; OriginalSymbolOrigin: (5080,5080); OLDCOMPONENTID: 190; MAXGCOUNT: 1; COMPONENTNAME: GDM010001044; MFSOLDERINGPROP: .; OUMEMAKER: NAE 松下電子部品; MFPACKAGEMETHOP: S; MFFORMINGDIVP: KC; MOUNTINGFORMSMD: SMD; OUMECLASSIFICATION: 表面実装用固定抵抗器; RESISTANCETOLER: F; MFMOUNTSYMBOLP: 80; POWERRATING: 63m; OUMEMAKERKATAMEI: ERJ3GEYF202V; NOMINALRESISTAN: 2K; NUMBEROFELEMENT: 0; VAL2: 62.5mW; CDMASTERCADCELG: DR802R; PCODE: P01042243622; FNCLASSCODEG: P01-08
R4 = R_Dup1: SQ_PART_MODEL: RES_2K; FNPARTSNAMEG: CHIP RESISTOR (1608); USEINPARTSLIST: YES; OriginalSymbolOrigin: (5080,5080); OLDCOMPONENTID: 360; MAXGCOUNT: 1; COMPONENTNAME: GDM010001044; MFSOLDERINGPROP: .; OUMEMAKER: NAE 松下電子部品; MFPACKAGEMETHOP: S; MFFORMINGDIVP: KC; MOUNTINGFORMSMD: SMD; OUMECLASSIFICATION: 表面実装用固定抵抗器; RESISTANCETOLER: F; MFMOUNTSYMBOLP: 80; POWERRATING: 63m; OUMEMAKERKATAMEI: ERJ3GEYF202V; NOMINALRESISTAN: 2K; NUMBEROFELEMENT: 0; VAL2: 62.5mW; CDMASTERCADCELG: DR802R; PCODE: P01042243622; FNCLASSCODEG: P01-08
R5 = R_Dup1: SQ_PART_MODEL: RES_100K; FNPARTSNAMEG: CHIP RESISTOR (1608); USEINPARTSLIST: YES; OriginalSymbolOrigin: (5080,5080); OLDCOMPONENTID: 330; TOLERANCE: J; ASIMVALUE: 100K; MFSOLDERINGPROP: .; MFPACKAGEMETHOP: S; MFFORMINGDIVP: KC; MOUNTINGFORMSMD: SMD; MFMOUNTSYMBOLP: 80; NUMBEROFELEMENT: 0; PCODE: P01042047220; MAXGCOUNT: 1; COMPONENTNAME: G36010011057; OUMEMAKER: HDK 北陸電気工業; OUMECLASSIFICATION: 表面実装用固定抵抗器; POWERRATING: 63m; OUMEMAKERKATAMEI: CR1/16 104JV; VAL2: 62.5mW; CDMASTERCADCELG: DR802R; FNCLASSCODEG: P01-08
R6 = R_Dup1: SQ_PART_MODEL: RES_10; FNPARTSNAMEG: CHIP RESISTOR (1608); USEINPARTSLIST: YES; OriginalSymbolOrigin: (5080,5080); OLDCOMPONENTID: 333; TOLERANCE: F; ASIMVALUE: 10; MFSOLDERINGPROP: .; MFPACKAGEMETHOP: S; MFFORMINGDIVP: KC; MOUNTINGFORMSMD: SMD; MFMOUNTSYMBOLP: 80; NUMBEROFELEMENT: 0; PCODE: P01042036620; MAXGCOUNT: 1; COMPONENTNAME: G36010104063; OUMEMAKER: NAE 松下電子部品; OUMECLASSIFICATION: 表面実装用固定抵抗器; POWERRATING: 63m; OUMEMAKERKATAMEI: ERJ3GEYF100V; VAL2: 62.5mW; VAL1: 10(F); CDMASTERCADCELG: DR802R; FNCLASSCODEG: P01-08
R7 = R_Dup1: SQ_PART_MODEL: RES_100K; FNPARTSNAMEG: CHIP RESISTOR (1608); USEINPARTSLIST: YES; OriginalSymbolOrigin: (5080,5080); OLDCOMPONENTID: 390; TOLERANCE: J; ASIMVALUE: 100K; MFSOLDERINGPROP: .; MFPACKAGEMETHOP: S; MFFORMINGDIVP: KC; MOUNTINGFORMSMD: SMD; MFMOUNTSYMBOLP: 80; NUMBEROFELEMENT: 0; PCODE: P01042047220; MAXGCOUNT: 1; COMPONENTNAME: G36010011057; OUMEMAKER: HDK 北陸電気工業; OUMECLASSIFICATION: 表面実装用固定抵抗器; POWERRATING: 63m; OUMEMAKERKATAMEI: CR1/16 104JV; VAL2: 62.5mW; CDMASTERCADCELG: DR802R; FNCLASSCODEG: P01-08
R8 = R_Dup1: SQ_PART_MODEL: RES_10; FNPARTSNAMEG: CHIP RESISTOR (1608); USEINPARTSLIST: YES; OriginalSymbolOrigin: (5080,5080); OLDCOMPONENTID: 354; TOLERANCE: F; ASIMVALUE: 10; MFSOLDERINGPROP: .; MFPACKAGEMETHOP: S; MFFORMINGDIVP: KC; MOUNTINGFORMSMD: SMD; MFMOUNTSYMBOLP: 80; NUMBEROFELEMENT: 0; PCODE: P01042036620; MAXGCOUNT: 1; COMPONENTNAME: G36010104063; OUMEMAKER: NAE 松下電子部品; OUMECLASSIFICATION: 表面実装用固定抵抗器; POWERRATING: 63m; OUMEMAKERKATAMEI: ERJ3GEYF100V; VAL2: 62.5mW; VAL1: 10(F); CDMASTERCADCELG: DR802R; FNCLASSCODEG: P01-08
R9 = R_Dup1: SQ_PART_MODEL: RES_27K; FNPARTSNAMEG: CHIP RESISTOR (1608); USEINPARTSLIST: YES; OriginalSymbolOrigin: (5080,5080); OLDCOMPONENTID: 236; MAXGCOUNT: 1; TOLERANCE: F; COMPONENTNAME: G36010027195; MFSOLDERINGPROP: .; OUMEMAKER: NAE 松下電子部品; MFPACKAGEMETHOP: S; MFFORMINGDIVP: KC; MOUNTINGFORMSMD: SMD; OUMECLASSIFICATION: 表面実装用固定抵抗器; ASIMVALUE: 27K; MFMOUNTSYMBOLP: 80; POWERRATING: 63m; OUMEMAKERKATAMEI: ERJ3GEYF273V; NUMBEROFELEMENT: 0; VAL2: 62.5mW; CDMASTERCADCELG: DR802R; PCODE: P01042508622; FNCLASSCODEG: P01-08
R10 = R_Dup1: SQ_PART_MODEL: RES_160K; FNPARTSNAMEG: CHIP RESISTOR (1608); USEINPARTSLIST: YES; OriginalSymbolOrigin: (5080,5080); OLDCOMPONENTID: 162; MAXGCOUNT: 1; COMPONENTNAME: G51011061108; MFSOLDERINGPROP: .; OUMEMAKER: HDK 北陸電気工業; MFPACKAGEMETHOP: S; MFFORMINGDIVP: KC; MOUNTINGFORMSMD: SMD; OUMECLASSIFICATION: 表面実装用固定抵抗器; RESISTANCETOLER: F; MFMOUNTSYMBOLP: 80; POWERRATING: 63m; OUMEMAKERKATAMEI: CR1/16 164FV; NOMINALRESISTAN: 160K; NUMBEROFELEMENT: 0; VAL2: 62.5mW; CDMASTERCADCELG: DR802R; PCODE: P01042125225; FNCLASSCODEG: P01-08
R11 = R_Dup1: SQ_PART_MODEL: RES_27K; FNPARTSNAMEG: CHIP RESISTOR (1608); USEINPARTSLIST: YES; OriginalSymbolOrigin: (5080,5080); OLDCOMPONENTID: 381; MAXGCOUNT: 1; TOLERANCE: F; COMPONENTNAME: G36010027195; MFSOLDERINGPROP: .; OUMEMAKER: NAE 松下電子部品; MFPACKAGEMETHOP: S; MFFORMINGDIVP: KC; MOUNTINGFORMSMD: SMD; OUMECLASSIFICATION: 表面実装用固定抵抗器; ASIMVALUE: 27K; MFMOUNTSYMBOLP: 80; POWERRATING: 63m; OUMEMAKERKATAMEI: ERJ3GEYF273V; NUMBEROFELEMENT: 0; VAL2: 62.5mW; CDMASTERCADCELG: DR802R; PCODE: P01042508622; FNCLASSCODEG: P01-08
R12 = R_Dup1: SQ_PART_MODEL: RES_160K; FNPARTSNAMEG: CHIP RESISTOR (1608); USEINPARTSLIST: YES; OriginalSymbolOrigin: (5080,5080); OLDCOMPONENTID: 380; MAXGCOUNT: 1; COMPONENTNAME: G51011061108; MFSOLDERINGPROP: .; OUMEMAKER: HDK 北陸電気工業; MFPACKAGEMETHOP: S; MFFORMINGDIVP: KC; MOUNTINGFORMSMD: SMD; OUMECLASSIFICATION: 表面実装用固定抵抗器; RESISTANCETOLER: F; MFMOUNTSYMBOLP: 80; POWERRATING: 63m; OUMEMAKERKATAMEI: CR1/16 164FV; NOMINALRESISTAN: 160K; NUMBEROFELEMENT: 0; VAL2: 62.5mW; CDMASTERCADCELG: DR802R; PCODE: P01042125225; FNCLASSCODEG: P01-08
R13 = R_Dup1: SQ_PART_MODEL: RES_10; FNPARTSNAMEG: CHIP RESISTOR (1608); USEINPARTSLIST: YES; OriginalSymbolOrigin: (5080,5080); OLDCOMPONENTID: 167; TOLERANCE: F; ASIMVALUE: 10; MFSOLDERINGPROP: .; MFPACKAGEMETHOP: S; MFFORMINGDIVP: KC; MOUNTINGFORMSMD: SMD; MFMOUNTSYMBOLP: 80; PCODE: P01042036620; MAXGCOUNT: 1; COMPONENTNAME: G36010104063; OUMEMAKER: NAE 松下電子部品; OUMECLASSIFICATION: 表面実装用固定抵抗器; POWERRATING: 63m; OUMEMAKERKATAMEI: ERJ3GEYF100V; VAL2: 62.5mW; CDMASTERCADCELG: DR802R; FNCLASSCODEG: P01-08
R14 = R_Dup1: SQ_PART_MODEL: RES_10; FNPARTSNAMEG: CHIP RESISTOR (2012); USEINPARTSLIST: YES; OriginalSymbolOrigin: (5080,5080); OLDCOMPONENTID: 188; MAXGCOUNT: 1; TOLERANCE: F; COMPONENTNAME: 5P9L1083P100; MFSOLDERINGPROP: .; OUMEMAKER: 北陸電気工業; MFPACKAGEMETHOP: S; MFFORMINGDIVP: KC; MOUNTINGFORMSMD: SMD; OUMECLASSIFICATION: 表面実装用固定抵抗器; ASIMVALUE: 10; MFMOUNTSYMBOLP: 90; POWERRATING: 100m; OUMEMAKERKATAMEI: CR1/10 100FV Pb(F); VAL2: 125mW; CDMASTERCADCELG: DR910A; PCODE: P01043091222; FNCLASSCODEG: P01-08
R15 = R_Dup1: SQ_PART_MODEL: RES_10; FNPARTSNAMEG: CHIP RESISTOR (1608); USEINPARTSLIST: YES; OriginalSymbolOrigin: (5080,5080); OLDCOMPONENTID: 369; TOLERANCE: F; ASIMVALUE: 10; MFSOLDERINGPROP: .; MFPACKAGEMETHOP: S; MFFORMINGDIVP: KC; MOUNTINGFORMSMD: SMD; MFMOUNTSYMBOLP: 80; PCODE: P01042036620; MAXGCOUNT: 1; COMPONENTNAME: G36010104063; OUMEMAKER: NAE 松下電子部品; OUMECLASSIFICATION: 表面実装用固定抵抗器; POWERRATING: 63m; OUMEMAKERKATAMEI: ERJ3GEYF100V; VAL2: 62.5mW; CDMASTERCADCELG: DR802R; FNCLASSCODEG: P01-08
R16 = R_Dup1: SQ_PART_MODEL: RES_10; FNPARTSNAMEG: CHIP RESISTOR (2012); USEINPARTSLIST: YES; OriginalSymbolOrigin: (5080,5080); OLDCOMPONENTID: 394; MAXGCOUNT: 1; TOLERANCE: F; COMPONENTNAME: 5P9L1083P100; MFSOLDERINGPROP: .; OUMEMAKER: 北陸電気工業; MFPACKAGEMETHOP: S; MFFORMINGDIVP: KC; MOUNTINGFORMSMD: SMD; OUMECLASSIFICATION: 表面実装用固定抵抗器; ASIMVALUE: 10; MFMOUNTSYMBOLP: 90; POWERRATING: 100m; OUMEMAKERKATAMEI: CR1/10 100FV Pb(F); VAL2: 125mW; CDMASTERCADCELG: DR910A; PCODE: P01043091222; FNCLASSCODEG: P01-08
R17 = R_Dup1: SQ_PART_MODEL: RES_10; FNPARTSNAMEG: CHIP RESISTOR (2012); USEINPARTSLIST: YES; OriginalSymbolOrigin: (5080,5080); OLDCOMPONENTID: 180; MAXGCOUNT: 1; TOLERANCE: F; COMPONENTNAME: 5P9L1083P100; MFSOLDERINGPROP: .; OUMEMAKER: 北陸電気工業; MFPACKAGEMETHOP: S; MFFORMINGDIVP: KC; MOUNTINGFORMSMD: SMD; OUMECLASSIFICATION: 表面実装用固定抵抗器; ASIMVALUE: 10; MFMOUNTSYMBOLP: 90; POWERRATING: 100m; OUMEMAKERKATAMEI: CR1/10 100FV Pb(F); VAL2: 125mW; CDMASTERCADCELG: DR910A; PCODE: P01043091222; FNCLASSCODEG: P01-08
R18 = R_Dup1: SQ_PART_MODEL: RES_10; FNPARTSNAMEG: CHIP RESISTOR (2012); USEINPARTSLIST: YES; OriginalSymbolOrigin: (5080,5080); OLDCOMPONENTID: 391; MAXGCOUNT: 1; TOLERANCE: F; COMPONENTNAME: 5P9L1083P100; MFSOLDERINGPROP: .; OUMEMAKER: 北陸電気工業; MFPACKAGEMETHOP: S; MFFORMINGDIVP: KC; MOUNTINGFORMSMD: SMD; OUMECLASSIFICATION: 表面実装用固定抵抗器; ASIMVALUE: 10; MFMOUNTSYMBOLP: 90; POWERRATING: 100m; OUMEMAKERKATAMEI: CR1/10 100FV Pb(F); VAL2: 125mW; CDMASTERCADCELG: DR910A; PCODE: P01043091222; FNCLASSCODEG: P01-08
R19 = R_Dup1: SQ_PART_MODEL: RES_4.3K; FNPARTSNAMEG: CHIP RESISTOR (1608); USEINPARTSLIST: YES; OriginalSymbolOrigin: (5080,5080); OLDCOMPONENTID: 158; MAXGCOUNT: 1; COMPONENTNAME: G36010027201; MFSOLDERINGPROP: .; OUMEMAKER: NAE 松下電子部品; MFPACKAGEMETHOP: S; MFFORMINGDIVP: KC; MOUNTINGFORMSMD: SMD; OUMECLASSIFICATION: 表面実装用固定抵抗器; RESISTANCETOLER: F; MFMOUNTSYMBOLP: 80; POWERRATING: 63m; OUMEMAKERKATAMEI: ERJ3GEYF432V; NOMINALRESISTAN: 4.3K; NUMBEROFELEMENT: 0; VAL2: 62.5mW; CDMASTERCADCELG: DR802R; PCODE: P01042335624; FNCLASSCODEG: P01-08
R20 = R_Dup1: SQ_PART_MODEL: RES_4.3K; FNPARTSNAMEG: CHIP RESISTOR (1608); USEINPARTSLIST: YES; OriginalSymbolOrigin: (5080,5080); OLDCOMPONENTID: 370; MAXGCOUNT: 1; COMPONENTNAME: G36010027201; MFSOLDERINGPROP: .; OUMEMAKER: NAE 松下電子部品; MFPACKAGEMETHOP: S; MFFORMINGDIVP: KC; MOUNTINGFORMSMD: SMD; OUMECLASSIFICATION: 表面実装用固定抵抗器; RESISTANCETOLER: F; MFMOUNTSYMBOLP: 80; POWERRATING: 63m; OUMEMAKERKATAMEI: ERJ3GEYF432V; NOMINALRESISTAN: 4.3K; NUMBEROFELEMENT: 0; VAL2: 62.5mW; CDMASTERCADCELG: DR802R; PCODE: P01042335624; FNCLASSCODEG: P01-08
R21 = R_Dup1: SQ_PART_MODEL: RES_82K; FNPARTSNAMEG: CHIP RESISTOR (1608); USEINPARTSLIST: YES; OriginalSymbolOrigin: (5080,5080); OLDCOMPONENTID: 235; TOLERANCE: F; ASIMVALUE: 82K; MAXGCOUNT: 1; COMPONENTNAME: G36010027317; MFSOLDERINGPROP: .; OUMEMAKER: KOA ＫＯＡ; MFPACKAGEMETHOP: S; MFFORMINGDIVP: KC; MOUNTINGFORMSMD: SMD; OUMECLASSIFICATION: 表面実装用固定抵抗器; MFMOUNTSYMBOLP: 80; POWERRATING: 63m; OUMEMAKERKATAMEI: RK73H1JTD8202F; NUMBEROFELEMENT: 0; VAL2: 62.5mW; VAL1: 82K(F); CDMASTERCADCELG: DR802R; PCODE: P01042496424; FNCLASSCODEG: P01-08
R22 = R_Dup1: SQ_PART_MODEL: RES_82K; FNPARTSNAMEG: CHIP RESISTOR (1608); USEINPARTSLIST: YES; OriginalSymbolOrigin: (5080,5080); OLDCOMPONENTID: 353; TOLERANCE: F; ASIMVALUE: 82K; MAXGCOUNT: 1; COMPONENTNAME: G36010027317; MFSOLDERINGPROP: .; OUMEMAKER: KOA ＫＯＡ; MFPACKAGEMETHOP: S; MFFORMINGDIVP: KC; MOUNTINGFORMSMD: SMD; OUMECLASSIFICATION: 表面実装用固定抵抗器; MFMOUNTSYMBOLP: 80; POWERRATING: 63m; OUMEMAKERKATAMEI: RK73H1JTD8202F; NUMBEROFELEMENT: 0; VAL2: 62.5mW; VAL1: 82K(F); CDMASTERCADCELG: DR802R; PCODE: P01042496424; FNCLASSCODEG: P01-08
R25 = R_Dup1: SQ_PART_MODEL: RES_3.3K; FNPARTSNAMEG: CHIP RESISTOR (1608); USEINPARTSLIST: YES; OriginalSymbolOrigin: (5080,5080); OLDCOMPONENTID: 205; MAXGCOUNT: 1; COMPONENTNAME: G36010014485; MFSOLDERINGPROP: .; OUMEMAKER: SSM 進工業; MFPACKAGEMETHOP: S; MFFORMINGDIVP: KC; MOUNTINGFORMSMD: SMD; OUMECLASSIFICATION: 表面実装用固定抵抗器; RESISTANCETOLER: D; MFMOUNTSYMBOLP: 80; POWERRATING: 63m; OUMEMAKERKATAMEI: RR0816P-332-D; NOMINALRESISTAN: 3.3K; NUMBEROFELEMENT: 0; VAL2: 62.5mW; CDMASTERCADCELG: DR802R; PCODE: P01042249822; FNCLASSCODEG: P01-08
R26 = R_Dup1: ICX_PART_MODEL: RES_8.2K; FNPARTSNAMEG: CHIP RESISTOR (1608); OriginalSymbolOrigin: (5080,5080); OLDCOMPONENTID: 225; FNCLASSCODEG: P01-08; PCODE: P01117051114; CDMASTERCADCELG: DR802R; USEWITHSCHEMA: YES; VAL2: 62.5mW; NUMBEROFELEMENT: 0; NOMINALRESISTAN: 8.2K; OUMEMAKERKATAMEI: RK73G1JTD822D; POWERRATING: 63m; MFMOUNTSYMBOLP: 80; RESISTANCETOLER: D; FUNCTION: G36010129479; OUMECLASSIFICATION: 表面実装用固定抵抗器; MOUNTINGFORMSMD: SMD; MFFORMINGDIVP: KC; MFPACKAGEMETHOP: S; OUMEMAKER: KOA ＫＯＡ; MFSOLDERINGPROP: .; MAXGCOUNT: 1
R27 = R_Dup1: SQ_PART_MODEL: RES_3.3K; FNPARTSNAMEG: CHIP RESISTOR (1608); USEINPARTSLIST: YES; OriginalSymbolOrigin: (5080,5080); OLDCOMPONENTID: 383; MAXGCOUNT: 1; COMPONENTNAME: G36010014485; MFSOLDERINGPROP: .; OUMEMAKER: SSM 進工業; MFPACKAGEMETHOP: S; MFFORMINGDIVP: KC; MOUNTINGFORMSMD: SMD; OUMECLASSIFICATION: 表面実装用固定抵抗器; RESISTANCETOLER: D; MFMOUNTSYMBOLP: 80; POWERRATING: 63m; OUMEMAKERKATAMEI: RR0816P-332-D; NOMINALRESISTAN: 3.3K; NUMBEROFELEMENT: 0; VAL2: 62.5mW; CDMASTERCADCELG: DR802R; PCODE: P01042249822; FNCLASSCODEG: P01-08
R28 = R_Dup1: ICX_PART_MODEL: RES_8.2K; FNPARTSNAMEG: CHIP RESISTOR (1608); OriginalSymbolOrigin: (5080,5080); OLDCOMPONENTID: 401; FNCLASSCODEG: P01-08; PCODE: P01117051114; CDMASTERCADCELG: DR802R; USEWITHSCHEMA: YES; VAL2: 62.5mW; NUMBEROFELEMENT: 0; NOMINALRESISTAN: 8.2K; OUMEMAKERKATAMEI: RK73G1JTD822D; POWERRATING: 63m; MFMOUNTSYMBOLP: 80; RESISTANCETOLER: D; FUNCTION: G36010129479; OUMECLASSIFICATION: 表面実装用固定抵抗器; MOUNTINGFORMSMD: SMD; MFFORMINGDIVP: KC; MFPACKAGEMETHOP: S; OUMEMAKER: KOA ＫＯＡ; MFSOLDERINGPROP: .; MAXGCOUNT: 1
R29 = R_Dup1: SQ_PART_MODEL: RES_3.3K; FNPARTSNAMEG: CHIP RESISTOR (1608); USEINPARTSLIST: YES; OriginalSymbolOrigin: (5080,5080); OLDCOMPONENTID: 223; TOLERANCE: F; ASIMVALUE: 3.3K; MAXGCOUNT: 1; COMPONENTNAME: G36010027027; MFSOLDERINGPROP: .; OUMEMAKER: ROH ロー・; MFPACKAGEMETHOP: S; MFFORMINGDIVP: KC; MOUNTINGFORMSMD: SMD; OUMECLASSIFICATION: 表面実装用固定抵抗器; MFMOUNTSYMBOLP: 80; POWERRATING: 63m; OUMEMAKERKATAMEI: MCR03EZPFX3301; NUMBEROFELEMENT: 0; VAL2: 62.5mW; VAL1: 3.3K(F); CDMASTERCADCELG: DR802R; PCODE: P01042250729; FNCLASSCODEG: P01-08
R30 = R_Dup1: ICX_PART_MODEL: RES_680; FNPARTSNAMEG: CHIP RESISTOR (1608); OriginalSymbolOrigin: (5080,5080); OLDCOMPONENTID: 196; FNCLASSCODEG: P01-08; PCODE: P01117025115; CDMASTERCADCELG: DR802R; USEWITHSCHEMA: YES; VAL2: 62.5mW; NUMBEROFELEMENT: 0; NOMINALRESISTAN: 680; OUMEMAKERKATAMEI: RK73G1JTD681D; POWERRATING: 63m; MFMOUNTSYMBOLP: 80; RESISTANCETOLER: D; FUNCTION: G36010129219; OUMECLASSIFICATION: 表面実装用固定抵抗器; MOUNTINGFORMSMD: SMD; MFFORMINGDIVP: KC; MFPACKAGEMETHOP: S; OUMEMAKER: KOA ＫＯＡ; MFSOLDERINGPROP: .; MAXGCOUNT: 1
R31 = R_Dup1: SQ_PART_MODEL: RES_3.3K; FNPARTSNAMEG: CHIP RESISTOR (1608); USEINPARTSLIST: YES; OriginalSymbolOrigin: (5080,5080); OLDCOMPONENTID: 373; TOLERANCE: F; ASIMVALUE: 3.3K; MAXGCOUNT: 1; COMPONENTNAME: G36010027027; MFSOLDERINGPROP: .; OUMEMAKER: ROH ロー・; MFPACKAGEMETHOP: S; MFFORMINGDIVP: KC; MOUNTINGFORMSMD: SMD; OUMECLASSIFICATION: 表面実装用固定抵抗器; MFMOUNTSYMBOLP: 80; POWERRATING: 63m; OUMEMAKERKATAMEI: MCR03EZPFX3301; NUMBEROFELEMENT: 0; VAL2: 62.5mW; VAL1: 3.3K(F); CDMASTERCADCELG: DR802R; PCODE: P01042250729; FNCLASSCODEG: P01-08
R32 = R_Dup1: ICX_PART_MODEL: RES_680; FNPARTSNAMEG: CHIP RESISTOR (1608); OriginalSymbolOrigin: (5080,5080); OLDCOMPONENTID: 378; FNCLASSCODEG: P01-08; PCODE: P01117025115; CDMASTERCADCELG: DR802R; USEWITHSCHEMA: YES; VAL2: 62.5mW; NUMBEROFELEMENT: 0; NOMINALRESISTAN: 680; OUMEMAKERKATAMEI: RK73G1JTD681D; POWERRATING: 63m; MFMOUNTSYMBOLP: 80; RESISTANCETOLER: D; FUNCTION: G36010129219; OUMECLASSIFICATION: 表面実装用固定抵抗器; MOUNTINGFORMSMD: SMD; MFFORMINGDIVP: KC; MFPACKAGEMETHOP: S; OUMEMAKER: KOA ＫＯＡ; MFSOLDERINGPROP: .; MAXGCOUNT: 1
U?#1 = WAKU_DEF100: PLOTTIME: HH:MM; SAVEAREA0: 330961,54,387907,31546; TIME: 19:23:07; UPDATEUSER: t5459927; UPDATETIME: 15:26:28; SAVECOUNT: 6; OriginalSymbolOrigin: (10160,284480); DESIGNED: ***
